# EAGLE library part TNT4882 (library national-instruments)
High-Performance Single-Chip GPIB Talker/Listener ASIC Source: http://www.ni.com/pdf/products/us/0gpc763a.pdf http://www.ni.com/pdf/products/us/4gpib702-703.pdf
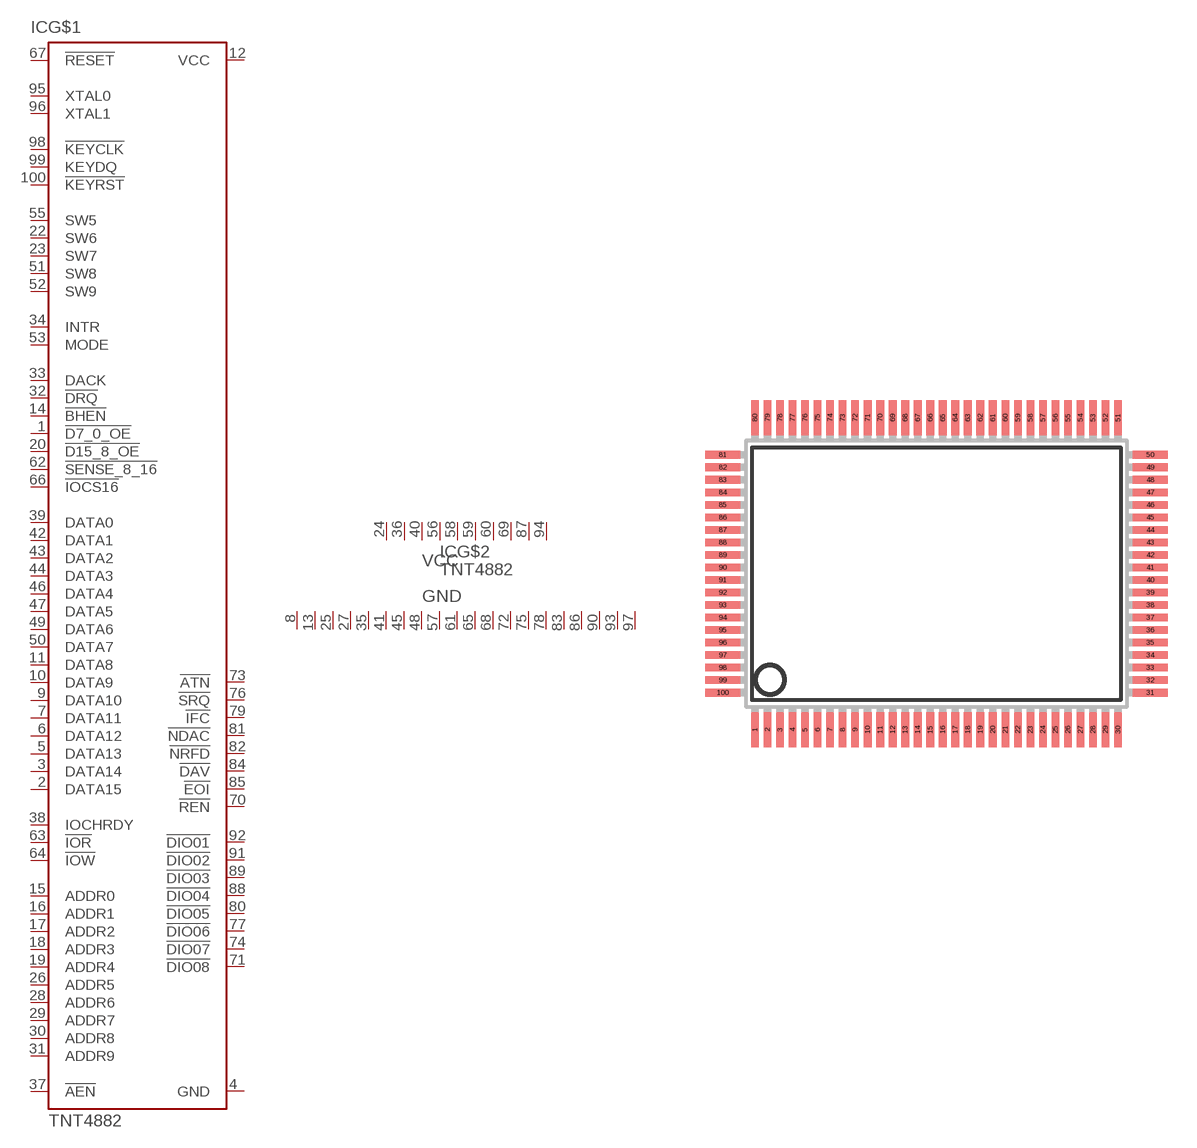
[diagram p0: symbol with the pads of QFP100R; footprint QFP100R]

Designator prefix IC; gates G$1=TNT4882 G$2=TNT4882-PWR

## TNT4882 (OC_FARNELL: unknown; OC_NEWARK: unknown)  [QFP100R]
1  G$1:!D7_0_OE  out
2  G$1:DATA15
3  G$1:DATA14
4  G$1:GND  pwr
5  G$1:DATA13
6  G$1:DATA12
7  G$1:DATA11
8  G$2:GND  pwr
9  G$1:DATA10
10  G$1:DATA9
11  G$1:DATA8
12  G$1:VCC  pwr
13  G$2:GND  pwr
14  G$1:!BHEN  in
15  G$1:ADDR0  in
16  G$1:ADDR1  in
17  G$1:ADDR2  in
18  G$1:ADDR3  in
19  G$1:ADDR4  in
20  G$1:!D15_8_OE  out
22  G$1:SW6  in
23  G$1:SW7  in
24  G$2:VCC  pwr
25  G$2:GND  pwr
26  G$1:ADDR5  in
27  G$2:GND  pwr
28  G$1:ADDR6  in
29  G$1:ADDR7  in
30  G$1:ADDR8  in
31  G$1:ADDR9  in
32  G$1:!DRQ  out
33  G$1:DACK  in
34  G$1:INTR  out
35  G$2:GND  pwr
36  G$2:VCC  pwr
37  G$1:!AEN  in
38  G$1:IOCHRDY  oc
39  G$1:DATA0
40  G$2:VCC  pwr
41  G$2:GND  pwr
42  G$1:DATA1
43  G$1:DATA2
44  G$1:DATA3
45  G$2:GND  pwr
46  G$1:DATA4
47  G$1:DATA5
48  G$2:GND  pwr
49  G$1:DATA6
50  G$1:DATA7
51  G$1:SW8  in
52  G$1:SW9  in
53  G$1:MODE  in
55  G$1:SW5  in
56  G$2:VCC  pwr
57  G$2:GND  pwr
58  G$2:VCC  pwr
59  G$2:VCC  pwr
60  G$2:VCC  pwr
61  G$2:GND  pwr
62  G$1:!SENSE_8_16  in
63  G$1:!IOR  in
64  G$1:!IOW  in
65  G$2:GND  pwr
66  G$1:!IOCS16  oc
67  G$1:!RESET  in
68  G$2:GND  pwr
69  G$2:VCC  pwr
70  G$1:!REN
71  G$1:!DIO08
72  G$2:GND  pwr
73  G$1:!ATN
74  G$1:!DIO07
75  G$2:GND  pwr
76  G$1:!SRQ
77  G$1:!DIO06
78  G$2:GND  pwr
79  G$1:!IFC
80  G$1:!DIO05
81  G$1:!NDAC
82  G$1:!NRFD
83  G$2:GND  pwr
84  G$1:!DAV
85  G$1:!EOI
86  G$2:GND  pwr
87  G$2:VCC  pwr
88  G$1:!DIO04
89  G$1:!DIO03
90  G$2:GND  pwr
91  G$1:!DIO02
92  G$1:!DIO01
93  G$2:GND  pwr
94  G$2:VCC  pwr
95  G$1:XTAL0  out
96  G$1:XTAL1  in
97  G$2:GND  pwr
98  G$1:!KEYCLK  out
99  G$1:KEYDQ
100  G$1:!KEYRST  out

## Footprint QFP100R (pad centres in mm)
Quad Flat Pack Package 100 Pin Rectangle Source: http://www.national.com/packaging/mkt/vce100a.pdf
smd 0.4 x 1.8: 1 -9.425,-8.1; 2 -8.775,-8.1; 3 -8.125,-8.1; 4 -7.475,-8.1; 5 -6.825,-8.1; 6 -6.175,-8.1; 7 -5.525,-8.1; 8 -4.875,-8.1; 9 -4.225,-8.1; 10 -3.575,-8.1; 11 -2.925,-8.1; 12 -2.275,-8.1; 13 -1.625,-8.1; 14 -0.975,-8.1; 15 -0.325,-8.1; 16 0.325,-8.1; 17 0.975,-8.1; 18 1.625,-8.1; 19 2.275,-8.1; 20 2.925,-8.1; 21 3.575,-8.1; 22 4.225,-8.1; 23 4.875,-8.1; 24 5.525,-8.1; 25 6.175,-8.1; 26 6.825,-8.1; 27 7.475,-8.1; 28 8.125,-8.1; 29 8.775,-8.1; 30 9.425,-8.1; 51 9.425,8.1; 52 8.775,8.1; 53 8.125,8.1; 54 7.475,8.1; 55 6.825,8.1; 56 6.175,8.1; 57 5.525,8.1; 58 4.875,8.1; 59 4.225,8.1; 60 3.575,8.1; 61 2.925,8.1; 62 2.275,8.1; 63 1.625,8.1; 64 0.975,8.1; 65 0.325,8.1; 66 -0.325,8.1; 67 -0.975,8.1; 68 -1.625,8.1; 69 -2.275,8.1; 70 -2.925,8.1; 71 -3.575,8.1; 72 -4.225,8.1; 73 -4.875,8.1; 74 -5.525,8.1; 75 -6.175,8.1; 76 -6.825,8.1; 77 -7.475,8.1; 78 -8.125,8.1; 79 -8.775,8.1; 80 -9.425,8.1
smd 1.8 x 0.4: 31 11.1,-6.175; 32 11.1,-5.525; 33 11.1,-4.875; 34 11.1,-4.225; 35 11.1,-3.575; 36 11.1,-2.925; 37 11.1,-2.275; 38 11.1,-1.625; 39 11.1,-0.975; 40 11.1,-0.325; 41 11.1,0.325; 42 11.1,0.975; 43 11.1,1.625; 44 11.1,2.275; 45 11.1,2.925; 46 11.1,3.575; 47 11.1,4.225; 48 11.1,4.875; 49 11.1,5.525; 50 11.1,6.175; 81 -11.1,6.175; 82 -11.1,5.525; 83 -11.1,4.875; 84 -11.1,4.225; 85 -11.1,3.575; 86 -11.1,2.925; 87 -11.1,2.275; 88 -11.1,1.625; 89 -11.1,0.975; 90 -11.1,0.325; 91 -11.1,-0.325; 92 -11.1,-0.975; 93 -11.1,-1.625; 94 -11.1,-2.275; 95 -11.1,-2.925; 96 -11.1,-3.575; 97 -11.1,-4.225; 98 -11.1,-4.875; 99 -11.1,-5.525; 100 -11.1,-6.175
